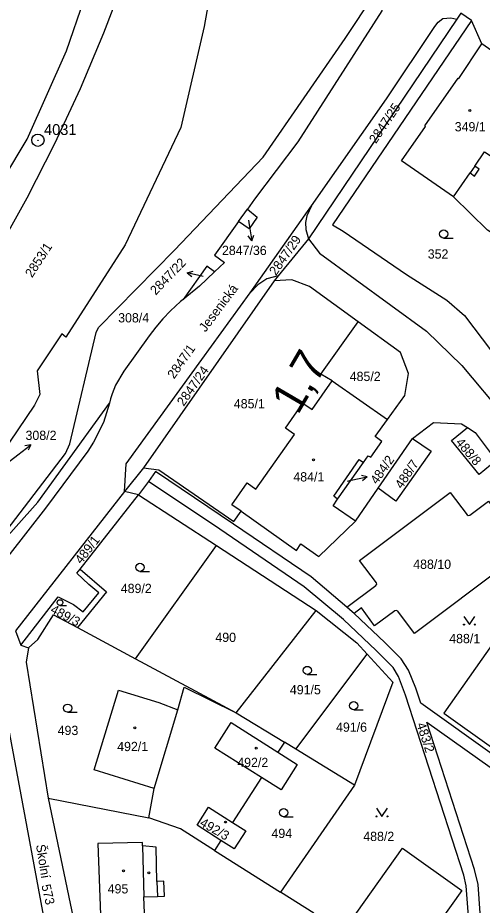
# Model space of a CAD drawing. Extents: x -558358 to -557517, y -1073785 to -1073189.
# Drawn here: x -558075.5 to -557990.2, y -1073433.5 to -1073270.7 of the extents above; entities that cross this region are included whole.
import ezdxf

# ---------------------------------------------------------------- set-up
doc = ezdxf.new("R2010")
doc.units = 0
for name, color, linetype in [('Hranice parcel', 7, 'Continuous'), ('Kolej', 7, 'Continuous'), ('Návěst místo trati', 7, 'Continuous'), ('Parcelní čísla', 7, 'Continuous'), ('Pop  PČ popisy', 7, 'Continuous'), ('Svazek obcí údolí Desné', 7, 'Continuous'), ('Vnitřní kresba', 7, 'Continuous'), ('Vrstva 60', 7, 'Continuous'), ('Značky budov', 7, 'Continuous'), ('Značky kultur', 7, 'Continuous')]:
    doc.layers.add(name, color=color, linetype=linetype)

msp = doc.modelspace()

# ---------------------------------------------------------------- linework, layer by layer
at = {"layer": 'Hranice parcel'}
for p, q in [((-557994.13, -1073269.82), (-557994.86, -1073270.9)), ((-557992.18, -1073271.14), (-557994.13, -1073269.82)), ((-557994.86, -1073270.9), (-558022.09, -1073311.21)), ((-557995.96, -1073270.7), (-557994.86, -1073270.9)), ((-557990.25, -1073275.48), (-557992.18, -1073271.14)), ((-558032.81, -1073321.13), (-558021.55, -1073305.19)), ((-558034.93, -1073308.06), (-558033.31, -1073305.78)), ((-558033.31, -1073305.78), (-558031.49, -1073307.27)), ((-558031.49, -1073307.27), (-558032.97, -1073309.39)), ((-558032.97, -1073309.39), (-558034.93, -1073308.06)), ((-558022.59, -1073309.53), (-558022.09, -1073311.21)), ((-558022.09, -1073311.21), (-558027.65, -1073318.03)), ((-558037.52, -1073315.57), (-558039.34, -1073317.31)), ((-558039.34, -1073317.31), (-558042.1, -1073319.93)), ((-558027.65, -1073318.03), (-558029.72, -1073318.58)), ((-558027.65, -1073318.03), (-558028.41, -1073318.97)), ((-558028.41, -1073318.97), (-558052.39, -1073353.27)), ((-558042.1, -1073319.93), (-558045.13, -1073322.4)), ((-558045.13, -1073322.4), (-558045.59, -1073322.77)), ((-558017.77, -1073337.32), (-558007.59, -1073344.4)), ((-558058.64, -1073341.4), (-558059.76, -1073344.95)), ((-558058.43, -1073340.61), (-558058.64, -1073341.4)), ((-558009.3, -1073357), (-558003.01, -1073347.89)), ((-558003.01, -1073347.89), (-557999.59, -1073350.23)), ((-557999.59, -1073350.23), (-558006.08, -1073359.37)), ((-558055.85, -1073357.6), (-558055.56, -1073352.56)), ((-558016.74, -1073359.04), (-558011.99, -1073352.26)), ((-558052.39, -1073353.27), (-558055.85, -1073357.6)), ((-558051.46, -1073355.75), (-558053.32, -1073358.25)), ((-558055.85, -1073357.6), (-558075.89, -1073383.19)), ((-558053.32, -1073358.25), (-558055.85, -1073357.6)), ((-558013.44, -1073363.06), (-558009.3, -1073357)), ((-558006.08, -1073359.37), (-558009.3, -1073357)), ((-558063.99, -1073371.84), (-558053.32, -1073358.25)), ((-558053.32, -1073358.25), (-558038.99, -1073367.55)), ((-558053.86, -1073388.3), (-558038.99, -1073367.55)), ((-558038.99, -1073367.55), (-558020.67, -1073379.44)), ((-558035.4, -1073398.23), (-558020.67, -1073379.44)), ((-558075.89, -1073383.19), (-558074.9, -1073385.82)), ((-558064.49, -1073382.58), (-558053.86, -1073388.3)), ((-558074.9, -1073385.82), (-558073.48, -1073386.28)), ((-558053.86, -1073388.3), (-558035.4, -1073398.23)), ((-558024.42, -1073404.91), (-558011.29, -1073387.48)), ((-558068.26, -1073448.76), (-558079.07, -1073390.9)), ((-558035.4, -1073398.23), (-558026.52, -1073403.63)), ((-558039.27, -1073404.7), (-558036.29, -1073400)), ((-558036.29, -1073400), (-558027.69, -1073405.45)), ((-558030.69, -1073410.09), (-558039.27, -1073404.7)), ((-558026.52, -1073403.63), (-558027.69, -1073405.45)), ((-558024.42, -1073404.91), (-558026.52, -1073403.63)), ((-558013.61, -1073411.49), (-558024.42, -1073404.91)), ((-558027.69, -1073405.45), (-558024.15, -1073407.69)), ((-558024.15, -1073407.69), (-558027.08, -1073412.36)), ((-558030.69, -1073410.09), (-558036.02, -1073418.35)), ((-558027.08, -1073412.36), (-558030.69, -1073410.09)), ((-558013.61, -1073411.49), (-558027.22, -1073431.17)), ((-558069.9, -1073413.89), (-558063.79, -1073443.12)), ((-558069.9, -1073413.89), (-558051.38, -1073417.49)), ((-558042.56, -1073418.87), (-558040.48, -1073415.56)), ((-558040.48, -1073415.56), (-558036.02, -1073418.35)), ((-558038.16, -1073421.67), (-558042.56, -1073418.87)), ((-558036.02, -1073418.35), (-558033.6, -1073419.86)), ((-558033.6, -1073419.86), (-558035.74, -1073423.21)), ((-558038.16, -1073421.67), (-558039.34, -1073423.5)), ((-558035.74, -1073423.21), (-558038.16, -1073421.67)), ((-558039.34, -1073423.5), (-558027.22, -1073431.17))]:
    msp.add_line(p, q, dxfattribs=at)
for points in [[(-557998.11, -1073217.81), (-557996.7, -1073222.28), (-557998.38, -1073242.39), (-558002.78, -1073257.43), (-558008.62, -1073269.37), (-558024.06, -1073293.44), (-558032.02, -1073303.96), (-558033.31, -1073305.78)], [(-558021.55, -1073305.19), (-558007.79, -1073285.56), (-557998.91, -1073272.25), (-557998.29, -1073271.45), (-557997.41, -1073270.82), (-557995.96, -1073270.7)], [(-557992.18, -1073271.14), (-558017.7, -1073308.66), (-558015.75, -1073309.85), (-558004.08, -1073317.8), (-557996.67, -1073322.48), (-557993.43, -1073325.31), (-557988.49, -1073331.84)], [(-557995.47, -1073303.55), (-558004.99, -1073296.92), (-558000.61, -1073290.62), (-558000.75, -1073290.52), (-557994.62, -1073281.73), (-557994.47, -1073281.84), (-557990.25, -1073275.48)], [(-557995.47, -1073303.55), (-557992.42, -1073299.14), (-557991.6, -1073299.71), (-557990.74, -1073298.46), (-557991.57, -1073297.9), (-557989.74, -1073295.26), (-557987.45, -1073296.82), (-557987.09, -1073296.7), (-557984.08, -1073292.32), (-557984.13, -1073291.92), (-557983.12, -1073290.42), (-557984.28, -1073289.64), (-557980.42, -1073284.02), (-557980.45, -1073282.32), (-557980.68, -1073282.11), (-557990.25, -1073275.48)], [(-557977.43, -1073317.43), (-557989.2, -1073309.62), (-557995.47, -1073303.55)], [(-558021.55, -1073305.19), (-558022.41, -1073307.04), (-558022.62, -1073308.24), (-558022.59, -1073309.53)], [(-558034.93, -1073308.06), (-558039.34, -1073314.26), (-558037.52, -1073315.57)], [(-558022.09, -1073311.21), (-558020.08, -1073313.87), (-558000.41, -1073328.2), (-557993.92, -1073334.5), (-557986.04, -1073343.93), (-557967.1, -1073369.2), (-557918.24, -1073434.51), (-557914.64, -1073436.24), (-557909.55, -1073436.22), (-557905.05, -1073434.1), (-557902.57, -1073430.65), (-557891.22, -1073414.37), (-557877.97, -1073395.43)], [(-558039.34, -1073317.31), (-558040.78, -1073316.28), (-558045.13, -1073322.4)], [(-558029.72, -1073318.58), (-558031.41, -1073319.68), (-558032.81, -1073321.13)], [(-558012.98, -1073326.49), (-558021.93, -1073320.01), (-558025.13, -1073318.78), (-558028.41, -1073318.97)], [(-558055.56, -1073352.56), (-558041.67, -1073333.36), (-558032.81, -1073321.13)], [(-558045.59, -1073322.77), (-558047.44, -1073324.48), (-558048.82, -1073325.91), (-558050.13, -1073327.44), (-558051.32, -1073329.04), (-558056.02, -1073335.51), (-558057.5, -1073338.08), (-558058.16, -1073339.69), (-558058.43, -1073340.61)], [(-558017.77, -1073337.32), (-558019.82, -1073336.05), (-558012.98, -1073326.49)], [(-558007.59, -1073344.4), (-558004.4, -1073339.98), (-558003.75, -1073335.95), (-558005.22, -1073332.12), (-558012.98, -1073326.49)], [(-558034.47, -1073361.24), (-558036.19, -1073360.05), (-558033.38, -1073356.04), (-558031.73, -1073357.2), (-558024.67, -1073347.17), (-558026.34, -1073346.01), (-558023.11, -1073341.4), (-558021.44, -1073342.56), (-558017.77, -1073337.32)], [(-558083.8, -1073372.96), (-558071.77, -1073359.59), (-558059.92, -1073343.2), (-558058.64, -1073341.4)], [(-558011.99, -1073352.26), (-558011.14, -1073351.05), (-558010.65, -1073351.33), (-558008.6, -1073348.45), (-558009.82, -1073347.53), (-558007.59, -1073344.4)], [(-558059.76, -1073344.95), (-558061.55, -1073348.53), (-558062.6, -1073350.23), (-558070.37, -1073360.66), (-558089.91, -1073385.65), (-558114.04, -1073415.6), (-558119.93, -1073422.75), (-558120.74, -1073423.38), (-558121.71, -1073423.79), (-558122.74, -1073423.86)], [(-558003.01, -1073347.89), (-557999.15, -1073344.94), (-557994.02, -1073345.2), (-557992.92, -1073345.89)], [(-557987.64, -1073351.9), (-557990.77, -1073354.47), (-557995.82, -1073348.28), (-557992.92, -1073345.89)], [(-557992.92, -1073345.89), (-557991.47, -1073346.8), (-557987.64, -1073351.9)], [(-558016.74, -1073359.04), (-558017.42, -1073358.44), (-558012.76, -1073351.73), (-558011.99, -1073352.26)], [(-558052.39, -1073353.27), (-558049.55, -1073353.62), (-558035.82, -1073363.11), (-558034.47, -1073361.24)], [(-558015.07, -1073378.83), (-558021.62, -1073373.3), (-558035.88, -1073363.58), (-558050.18, -1073353.97), (-558051.46, -1073355.75)], [(-557997.16, -1073446.28), (-557996.18, -1073446.14), (-557992.37, -1073440.37), (-557993.13, -1073429.99), (-557993.58, -1073428.02), (-558004.25, -1073395), (-558005.55, -1073391.58), (-558006.57, -1073389.94), (-558009.69, -1073386.81), (-558015.69, -1073381.13), (-558022.86, -1073375.1), (-558038.38, -1073364.54), (-558051.46, -1073355.75)], [(-558015.07, -1073378.83), (-558009.7, -1073374.87), (-558009.55, -1073374.62), (-558009.63, -1073374.36), (-558012.72, -1073370.26), (-557996.07, -1073357.8), (-557992.97, -1073361.92), (-557992.74, -1073362.04), (-557992.48, -1073361.98), (-557989.05, -1073359.38), (-557985.61, -1073364.04), (-557988.36, -1073366.15), (-557988.52, -1073366.38), (-557988.48, -1073366.66), (-557985.4, -1073370.76), (-558002.63, -1073383.68), (-558005.71, -1073379.56), (-558005.98, -1073379.48), (-558006.26, -1073379.51), (-558009.96, -1073382.24), (-558012.37, -1073378.99), (-558013.71, -1073380.01)], [(-558013.44, -1073363.06), (-558017.55, -1073360.24), (-558016.74, -1073359.04)], [(-558034.47, -1073361.24), (-558024.32, -1073368.43), (-558023.47, -1073367.24), (-558020.17, -1073369.56), (-558013.44, -1073363.06)], [(-558074.9, -1073385.82), (-558068.06, -1073376.95), (-558065.25, -1073378.32), (-558063.46, -1073379.72), (-558060.6, -1073376.18), (-558062.42, -1073374.7), (-558064.61, -1073372.63), (-558063.99, -1073371.84)], [(-558063.99, -1073371.84), (-558059.19, -1073376.03), (-558064.49, -1073382.58)], [(-558013.71, -1073380.01), (-558014.05, -1073379.69), (-558015.07, -1073378.83)], [(-557973.25, -1073383.95), (-557982.53, -1073377.43), (-557997.25, -1073398.28), (-557988.03, -1073404.82), (-557981.86, -1073396.11), (-557980.74, -1073396.9), (-557978.29, -1073393.44), (-557979.41, -1073392.65), (-557973.25, -1073383.95)], [(-558073.48, -1073386.28), (-558071.82, -1073384.76), (-558068.89, -1073380.22), (-558064.49, -1073382.58)], [(-558020.67, -1073379.44), (-558013.21, -1073385.39), (-558011.29, -1073387.48)], [(-557986.61, -1073406.29), (-557987.5, -1073406.44), (-558001.47, -1073396.48), (-558002.38, -1073393.7), (-558003.7, -1073390.42), (-558005.05, -1073388.34), (-558008.08, -1073385.35), (-558013.71, -1073380.01)], [(-558073.48, -1073386.28), (-558073.96, -1073388.93), (-558069.9, -1073413.89)], [(-558011.29, -1073387.48), (-558006.6, -1073392.58), (-558013.61, -1073411.49)], [(-558051.38, -1073417.49), (-558050.42, -1073412.09), (-558061.44, -1073408.67), (-558056.95, -1073394.08), (-558049.56, -1073396.36), (-558046.09, -1073397.7), (-558044.91, -1073393.54), (-558035.4, -1073398.23)], [(-557990.11, -1073441.11), (-557990.95, -1073429.72), (-557991.6, -1073426.99), (-558000.34, -1073399.97), (-557986.42, -1073409.86), (-557979.13, -1073399.38), (-557977.23, -1073400.7), (-557975.75, -1073398.59), (-557966.19, -1073404.96)], [(-558039.34, -1073423.5), (-558045.61, -1073419.54), (-558051.38, -1073417.49)], [(-558049.8, -1073431.93), (-558048.54, -1073431.88), (-558048.64, -1073429.15), (-558049.91, -1073429.2), (-558050.08, -1073422.86), (-558052.56, -1073422.66), (-558052.57, -1073422.02), (-558060.76, -1073422.24), (-558060.26, -1073435.32), (-558052.21, -1073435.02), (-558052.32, -1073432.02), (-558049.8, -1073431.93)], [(-558023.22, -1073448.98), (-558004.82, -1073423.06), (-557993.94, -1073430.83), (-558002.36, -1073442.69), (-558001.05, -1073443.62)], [(-558024.27, -1073448.53), (-558022.77, -1073438.58), (-558021.1, -1073435.02), (-558027.22, -1073431.17)]]:
    msp.add_lwpolyline(points, dxfattribs=at)
at = {"layer": 'Kolej'}
msp.add_lwpolyline([(-558079.04, -1073313.09), (-558073.77, -1073303.7), (-558068.68, -1073293.77), (-558063.96, -1073283.66), (-558059.66, -1073273.45), (-558055.92, -1073263.64), (-558052.59, -1073253.84), (-558049.52, -1073243.71), (-558046.86, -1073233.73), (-558044.36, -1073223.02), (-558042.07, -1073212.37), (-558037.79, -1073192.43), (-558037.29, -1073190.09)], dxfattribs=at)
at = {"layer": 'Pop  PČ popisy'}
for p, q in [((-558033.09, -1073307.84), (-558032.96, -1073308.65)), ((-558032.96, -1073308.65), (-558032.49, -1073311.61)), ((-558032.49, -1073311.61), (-558032.15, -1073310.55)), ((-558032.49, -1073311.61), (-558033.14, -1073310.7)), ((-558044.37, -1073317.47), (-558043.29, -1073317.2)), ((-558041.45, -1073318.14), (-558044.37, -1073317.47)), ((-558044.37, -1073317.47), (-558043.51, -1073318.18)), ((-558075.47, -1073350.88), (-558073.1, -1073349.03)), ((-558073.1, -1073349.03), (-558074.2, -1073349.25)), ((-558073.1, -1073349.03), (-558073.59, -1073350.04)), ((-558078.72, -1073353.4), (-558075.47, -1073350.88)), ((-558014.95, -1073355.7), (-558014.23, -1073355.56)), ((-558014.23, -1073355.56), (-558011.3, -1073354.94)), ((-558011.3, -1073354.94), (-558012.38, -1073354.65)), ((-558011.3, -1073354.94), (-558012.17, -1073355.63))]:
    msp.add_line(p, q, dxfattribs=at)
at = {"layer": 'Svazek obcí údolí Desné'}
msp.add_line((-558083.8, -1073372.96), (-558066.74, -1073350.64), dxfattribs=at)
for points in [[(-558025.53, -1073189.39), (-558032.09, -1073212.63), (-558035.15, -1073249.33), (-558039.97, -1073265.01), (-558041.24, -1073272.26), (-558045.55, -1073290.79), (-558055.77, -1073312.33), (-558066.64, -1073329.29), (-558067.37, -1073328.67), (-558071.91, -1073335.47), (-558071.45, -1073339.78), (-558072.38, -1073341.74), (-558078.52, -1073350.81)], [(-558066.74, -1073350.64), (-558065.9, -1073348.86), (-558061.08, -1073328.44), (-558060.65, -1073327.54), (-558046.7, -1073313.29), (-558030.4, -1073296.27), (-558015.33, -1073274.48), (-558010.02, -1073266.4), (-558006.82, -1073259.79), (-558003.58, -1073251.39), (-558001.93, -1073245.63), (-558000.3, -1073233.47), (-558000.14, -1073230.76), (-558000.21, -1073228.76), (-558000.67, -1073225.31), (-558001.93, -1073222.03), (-558003.18, -1073219.55), (-558003.41, -1073218.32), (-558003.28, -1073217.31), (-558002.8, -1073216.38), (-558000.9, -1073214.81), (-557999.34, -1073213.91), (-558005.3, -1073194.99), (-558007.47, -1073189.35)], [(-558082.18, -1073306.93), (-558073.77, -1073292.96), (-558066.53, -1073276.76), (-558060.05, -1073257.85), (-558056.4, -1073244.89), (-558045.6, -1073201.5), (-558043.17, -1073190.09)]]:
    msp.add_lwpolyline(points, dxfattribs=at)
at = {"layer": 'Vnitřní kresba'}
for p, q in [((-557991.57, -1073297.9), (-557992.42, -1073299.14)), ((-558050.42, -1073412.09), (-558046.09, -1073397.7)), ((-558052.56, -1073422.66), (-558052.32, -1073432.02)), ((-558049.91, -1073429.2), (-558049.8, -1073431.93))]:
    msp.add_line(p, q, dxfattribs=at)
at = {"layer": 'Vrstva 60'}
msp.add_line((-558071.77, -1073293.15), (-558071.77, -1073293.15), dxfattribs=at)
msp.add_line((-558071.77, -1073293.15), (-558071.77, -1073293.15), dxfattribs=at)
for radius in [1.12, 0.045]:
    msp.add_circle((-558071.77, -1073293.15), radius, dxfattribs=at)
at = {"layer": 'Značky budov'}
for centre in [(-557992.44, -1073287.7), (-558021.18, -1073351.82), (-558053.98, -1073400.98), (-558031.67, -1073404.71), (-558037.33, -1073418.27), (-558056.04, -1073427.22), (-558051.4, -1073427.58)]:
    msp.add_circle(centre, 0.175, dxfattribs=at)
at = {"layer": 'Značky kultur'}
for p, q in [((-557997.27, -1073311.09), (-557995.52, -1073311.09)), ((-558053.04, -1073372.28), (-558051.29, -1073372.28)), ((-558067.72, -1073378.52), (-558066.5, -1073378.52)), ((-558022.31, -1073391.2), (-558020.56, -1073391.2)), ((-558066.32, -1073398.13), (-558064.57, -1073398.13)), ((-558013.78, -1073397.68), (-558012.03, -1073397.68)), ((-558026.66, -1073417.3), (-558024.91, -1073417.3))]:
    msp.add_line(p, q, dxfattribs=at)
for points in [[(-557993.54, -1073380.54), (-557992.54, -1073382.04), (-557991.54, -1073380.54)], [(-558009.6, -1073415.75), (-558008.6, -1073417.25), (-558007.6, -1073415.75)]]:
    msp.add_lwpolyline(points, dxfattribs=at)
for centre, radius in [((-557997.27, -1073310.34), 0.75), ((-558053.04, -1073371.53), 0.75), ((-558067.72, -1073378), 0.525), ((-557993.54, -1073382.04), 0.1), ((-557991.54, -1073382.04), 0.1), ((-558022.31, -1073390.45), 0.75), ((-558066.32, -1073397.38), 0.75), ((-558013.78, -1073396.93), 0.75), ((-558026.66, -1073416.55), 0.75), ((-558009.6, -1073417.25), 0.1), ((-558007.6, -1073417.25), 0.1)]:
    msp.add_circle(centre, radius, dxfattribs=at)

# ---------------------------------------------------------------- texts
at = {"layer": 'Návěst místo trati'}
msp.add_text('1,7', height=6, rotation=59.7051, dxfattribs=at).set_placement((-558024.05, -1073343.72))
at = {"layer": 'Parcelní čísla'}
for s, rotation, p in [('2847/25', 56, (-558009.7, -1073293.88)), ('2853/1', 57, (-558072.84, -1073318.48)), ('2847/29', 55, (-558028.06, -1073318.09)), ('2847/22', 46, (-558050.14, -1073321.67)), ('2847/1', 55, (-558046.76, -1073337.06)), ('2847/24', 55, (-558045, -1073342.08)), ('488/8', 310, (-557995.15, -1073348.66)), ('484/2', 55, (-558009.5, -1073356.42)), ('488/7', 56, (-558004.94, -1073357.25)), ('489/1', 52, (-558063.81, -1073371.04)), ('489/3', 332, (-558069.62, -1073379.77)), ('483/2', 288, (-558002.27, -1073400.31)), ('492/3', 330, (-558042.19, -1073418.87)), ('573', 283, (-558071.15, -1073429.91))]:
    msp.add_text(s, height=1.7, rotation=rotation, dxfattribs=at).set_placement(p)
for s, p in [('349/1', (-557995.24, -1073291.52)), ('2847/36', (-558037.98, -1073314.21)), ('352', (-558000.19, -1073314.87)), ('308/4', (-558057.04, -1073326.58)), ('485/2', (-558014.52, -1073337.34)), ('485/1', (-558035.8, -1073342.35)), ('308/2', (-558074.05, -1073348.15)), ('484/1', (-558024.87, -1073355.77)), ('488/10', (-558002.86, -1073371.81)), ('489/2', (-558056.56, -1073376.25)), ('490', (-558039.19, -1073385.23)), ('488/1', (-557996.25, -1073385.45)), ('491/5', (-558025.51, -1073394.84)), ('491/6', (-558017.03, -1073401.71)), ('493', (-558068.15, -1073402.31)), ('492/1', (-558057.22, -1073405.26)), ('492/2', (-558035.17, -1073408.19)), ('494', (-558028.89, -1073421.21)), ('488/2', (-558012.03, -1073421.76)), ('495', (-558058.97, -1073431.38))]:
    msp.add_text(s, height=1.7, dxfattribs=at).set_placement(p)
at = {"layer": 'Pop  PČ popisy'}
for s, rotation, p in [('Jesenická', 53, (-558041.01, -1073328.46)), ('Školní', 279, (-558072.13, -1073422.5))]:
    msp.add_text(s, height=1.7, rotation=rotation, dxfattribs=at).set_placement(p)
at = {"layer": 'Vrstva 60'}
msp.add_text('4031', height=2, dxfattribs=at).set_placement((-558070.64, -1073292.18))

doc.saveas('drawing.dxf')
